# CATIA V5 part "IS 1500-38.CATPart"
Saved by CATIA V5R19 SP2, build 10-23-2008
Part number: IS 1500-38
Bounding box of the stored display mesh (mm): x -37.351 to 37.351, y -37.351 to 37.351, z 0 to 186
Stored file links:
  C:\Users\Bora\Desktop\3D Katı model\IS serisi\IS 1500\IS 1500-38.CATPart
  C:\Program Files\Dassault Systemes\B19\intel_a\reffiles\standard\MetricThickPitch.txt
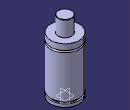
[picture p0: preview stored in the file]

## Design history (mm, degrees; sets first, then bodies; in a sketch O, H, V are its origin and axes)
Body1 (main body)
  Sketch1 on yz-plane, origin (0, 0, 0), H (0, 1, 0), V (0, 0, 1)
    point P1 (37.5, 129.5)
    point P2 (37.5, 124.5)
    point P5 (18, 185)
    point P7 (18, 185)
    point P12 (37.5, 124.5)
    point P13 (37.5, 129.5)
    arc A1 centre (37.5, 127) radius 2.5 from (37.5, 129.5) to (37.5, 124.5) ccw
    line L1 (37.5, 0) -> (37.5, 8)
    line L2 (18, 185) -> (18, 145)
    arc A2 centre (17, 185) radius 1 from (18, 185) to (17, 186) ccw
    line L3 (33.5, 13) -> (33.5, 8)
    line L4 (37.5, 13) -> (37.5, 124.5)
    line L5 (37.5, 129.5) -> (37.5, 145)
    line L6 (17, 186) -> (0, 186)
    line L7 (18, 145) -> (37.5, 145)
    line L8 (0, 0) -> (37.5, 0)
    line L9 (33.5, 13) -> (37.5, 13)
    line L10 (33.5, 8) -> (37.5, 8)
    horizontal: L6 H, L7 H, L8 H, L9 H, L10 H
    coincidence: P1 P13, P2 P12, P5 P7
  Shaft1: profile Sketch1, axis Sketch1.V, angle 360
  Sketch2 on face of Shaft1 from Sketch1.L8, origin (0, 0, 0), H (1, 0, 0), V (0, -1, 0)
    point P1 (20, 0)
    distance P1 V = 20
  Hole1: placed by Sketch2, at (20, 0, 0) direction (0, 0, 1), diameter 6.647, depth 13, threaded "M8", thread diameter 8, thread depth 13, pitch 1.25
  CircPattern1: of Hole1, instances 4, angular step 90, axis from xy-plane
